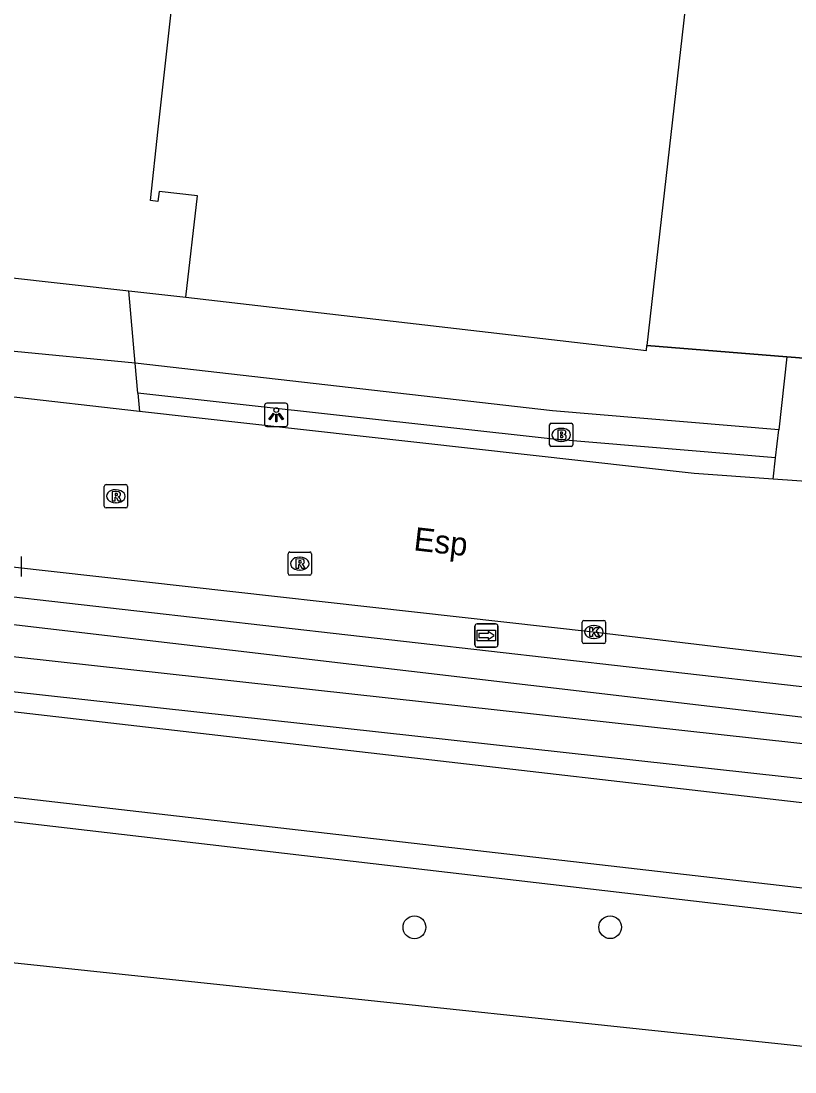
# Model space of a CAD drawing. Extents: x 161389 to 162585, y 388479 to 389761.
# Drawn here: x 162379.87 to 162413.12, y 388644.66 to 388689.82 of the extents above; entities that cross this region are included whole.
import ezdxf

# ---------------------------------------------------------------- set-up
doc = ezdxf.new("R2010")
doc.units = 0
for name, color, linetype in [('IMGEO_Berm_groen', 7, 'Continuous'), ('IMGEO_Boom', 7, 'Continuous'), ('IMGEO_Brandkraan', 7, 'Continuous'), ('IMGEO_Fietspad_gesloten', 7, 'Continuous'), ('IMGEO_Gemengd_bos', 7, 'Continuous'), ('IMGEO_Haag', 7, 'Continuous'), ('IMGEO_Hek', 7, 'Continuous'), ('IMGEO_Kolk', 7, 'Continuous'), ('IMGEO_Lichtpunt', 7, 'Continuous'), ('IMGEO_Openbare_ruimte_label', 7, 'Continuous'), ('IMGEO_Pand', 7, 'Continuous'), ('IMGEO_Rijbaan_lokaal_gesloten', 7, 'Continuous'), ('IMGEO_Rioolput', 7, 'Continuous'), ('IMGEO_Voetpad_open', 7, 'Continuous'), ('IMGEO_Waterloop', 7, 'Continuous'), ('IMGEO_Wegwijzer', 7, 'Continuous')]:
    doc.layers.add(name, color=color, linetype=linetype)

msp = doc.modelspace()

# ---------------------------------------------------------------- linework, layer by layer
at = {"layer": 'IMGEO_Berm_groen'}
for points in [[(162437.256, 388654.736), (162437.524, 388656.717), (162437.321, 388657.419), (162437.013, 388657.873), (162436.595, 388658.23), (162436.225, 388658.419), (162433.197, 388658.957), (162357.64, 388667.549)], [(162352.368, 388663.746), (162357.235, 388663.453), (162426.956, 388655.776), (162432.217, 388654.406), (162435.304, 388653.875)], [(162454.958, 388646.611), (162343.501, 388659.601)]]:
    msp.add_lwpolyline(points, dxfattribs=at)
at = {"layer": 'IMGEO_Boom'}
for centre in [(162396.77, 388650.877), (162405.18, 388650.883)]:
    msp.add_circle(centre, 0.489, dxfattribs=at)
at = {"layer": 'IMGEO_Brandkraan'}
for p, q in [((162402.578, 388671.612), (162402.578, 388672.464)), ((162402.653, 388672.538), (162403.505, 388672.538)), ((162403.066, 388672.318), (162403.091, 388672.318)), ((162403.579, 388672.464), (162403.579, 388671.612)), ((162403.505, 388671.538), (162402.653, 388671.538)), ((162403.089, 388671.758), (162403.064, 388671.758))]:
    msp.add_line(p, q, dxfattribs=at)
for points in [[(162402.578, 388671.612), (162402.578, 388672.464)], [(162402.653, 388672.538), (162403.505, 388672.538)], [(162403.579, 388672.464), (162403.579, 388671.612)], [(162402.926, 388672.238), (162402.926, 388671.838), (162403.139, 388671.838)], [(162403.157, 388672.238), (162402.926, 388672.238)], [(162403.105, 388672.157), (162403.051, 388672.157), (162403.051, 388672.081)], [(162403.051, 388672.081), (162403.104, 388672.081)], [(162403.113, 388672.005), (162403.051, 388672.005), (162403.051, 388671.924)], [(162403.051, 388671.924), (162403.113, 388671.924)], [(162403.505, 388671.538), (162402.653, 388671.538)]]:
    msp.add_lwpolyline(points, dxfattribs=at)
for centre, radius, start, end in [((162402.655, 388672.462), 0.0765, 91.552, 178.448), ((162402.655, 388672.462), 0.0765, 91.552, 178.448), ((162403.503, 388672.462), 0.0765, 1.552, 88.448), ((162403.503, 388672.462), 0.0765, 1.552, 88.448), ((162403.106, 388672.119), 0.0379, 267.8285, 90.9355), ((162403.114, 388671.964), 0.0404, 269.8759, 90.5077), ((162403.145, 388672.089), 0.251, 268.6676, 293.5347), ((162403.161, 388672.093), 0.145, 59.4692, 91.5367), ((162403.186, 388672.14), 0.0922, 285.5137, 58.1501), ((162403.191, 388671.948), 0.105, 301.3115, 78.989), ((162402.655, 388671.614), 0.0765, 181.552, 268.448), ((162402.655, 388671.614), 0.0765, 181.552, 268.448), ((162403.503, 388671.614), 0.0765, 271.552, 358.448), ((162403.503, 388671.614), 0.0765, 271.552, 358.448)]:
    msp.add_arc(centre, radius, start, end, dxfattribs=at)
for centre, major_axis, ratio, start_param, end_param in [((162403.065, 388672.038), (-0.387, 0.002), 0.722429, 4.712389, 7.853982), ((162403.09, 388672.038), (-0.39, 0.002), 0.717154, 1.570796, 4.712389)]:
    msp.add_ellipse(centre, major_axis=major_axis, ratio=ratio, start_param=start_param, end_param=end_param, dxfattribs=at)
at = {"layer": 'IMGEO_Fietspad_gesloten'}
for points in [[(162342.861, 388664.571), (162343.854, 388664.303), (162356.884, 388662.764), (162437.393, 388653.479), (162447.573, 388652.333)], [(162444.332, 388649.048), (162443.05, 388649.15), (162347.086, 388660.188)]]:
    msp.add_lwpolyline(points, dxfattribs=at)
at = {"layer": 'IMGEO_Gemengd_bos'}
msp.add_lwpolyline([(162341.543, 388653.38), (162458.56, 388641.004)], dxfattribs=at)
at = {"layer": 'IMGEO_Haag'}
for points in [[(162384.504, 388678.222), (162386.947, 388677.951)], [(162406.76, 388675.873), (162412.776, 388675.396)]]:
    msp.add_lwpolyline(points, dxfattribs=at)
at = {"layer": 'IMGEO_Hek'}
for points in [[(162412.776, 388675.396), (162406.76, 388675.873)], [(162420.122, 388674.813), (162412.776, 388675.396)]]:
    msp.add_lwpolyline(points, dxfattribs=at)
at = {"layer": 'IMGEO_Kolk'}
for p, q in [((162379.871, 388666.809), (162379.871, 388665.957)), ((162403.981, 388663.141), (162403.981, 388663.993)), ((162404.056, 388664.067), (162404.908, 388664.067)), ((162404.469, 388663.847), (162404.494, 388663.847)), ((162404.982, 388663.993), (162404.982, 388663.141)), ((162404.492, 388663.287), (162404.467, 388663.287)), ((162404.908, 388663.067), (162404.056, 388663.067))]:
    msp.add_line(p, q, dxfattribs=at)
for points in [[(162379.871, 388666.809), (162379.871, 388665.957)], [(162403.981, 388663.141), (162403.981, 388663.993)], [(162404.056, 388664.067), (162404.908, 388664.067)], [(162404.302, 388663.767), (162404.425, 388663.767), (162404.425, 388663.616), (162404.555, 388663.767), (162404.719, 388663.767), (162404.573, 388663.616), (162404.726, 388663.367), (162404.574, 388663.367), (162404.489, 388663.531), (162404.425, 388663.464), (162404.425, 388663.367), (162404.302, 388663.367), (162404.302, 388663.767)], [(162404.982, 388663.993), (162404.982, 388663.141)], [(162404.908, 388663.067), (162404.056, 388663.067)]]:
    msp.add_lwpolyline(points, dxfattribs=at)
for centre, start, end in [((162404.058, 388663.991), 91.552, 178.448), ((162404.058, 388663.991), 91.552, 178.448), ((162404.906, 388663.991), 1.552, 88.448), ((162404.906, 388663.991), 1.552, 88.448), ((162404.058, 388663.143), 181.552, 268.448), ((162404.058, 388663.143), 181.552, 268.448), ((162404.906, 388663.143), 271.552, 358.448), ((162404.906, 388663.143), 271.552, 358.448)]:
    msp.add_arc(centre, 0.0765, start, end, dxfattribs=at)
for centre, major_axis, ratio, start_param, end_param in [((162404.468, 388663.567), (-0.387, 0.002), 0.722429, 4.712389, 7.853982), ((162404.493, 388663.567), (-0.39, 0.002), 0.717154, 1.570796, 4.712389)]:
    msp.add_ellipse(centre, major_axis=major_axis, ratio=ratio, start_param=start_param, end_param=end_param, dxfattribs=at)
at = {"layer": 'IMGEO_Lichtpunt'}
for p, q in [((162390.337, 388673.304), (162390.337, 388672.497)), ((162390.337, 388673.304), (162390.337, 388672.497)), ((162391.239, 388673.399), (162390.431, 388673.399)), ((162391.239, 388673.399), (162390.431, 388673.399)), ((162391.333, 388672.497), (162391.333, 388673.304)), ((162391.333, 388672.497), (162391.333, 388673.304)), ((162390.431, 388672.403), (162391.239, 388672.403)), ((162390.431, 388672.403), (162391.239, 388672.403))]:
    msp.add_line(p, q, dxfattribs=at)
for points in [[(162390.711, 388672.968), (162390.75, 388672.94), (162390.562, 388672.678), (162390.524, 388672.705), (162390.711, 388672.968)], [(162390.813, 388672.92), (162390.86, 388672.92), (162390.86, 388672.598), (162390.813, 388672.598), (162390.813, 388672.92)], [(162390.923, 388672.94), (162390.961, 388672.967), (162391.148, 388672.705), (162391.109, 388672.677), (162390.923, 388672.94)]]:
    msp.add_lwpolyline(points, dxfattribs=at)
msp.add_circle((162390.836, 388673.102), 0.0994, dxfattribs=at)
for centre, start, end in [((162390.431, 388673.304), 90, 180), ((162390.431, 388673.304), 90, 180), ((162391.239, 388673.304), 0, 90), ((162391.239, 388673.304), 0, 90), ((162390.431, 388672.497), 180, 270), ((162390.431, 388672.497), 180, 270), ((162391.239, 388672.497), 270, 0), ((162391.239, 388672.497), 270, 360)]:
    msp.add_arc(centre, 0.0946, start, end, dxfattribs=at)
at = {"layer": 'IMGEO_Pand'}
for points in [[(162386.947, 388677.951), (162387.452, 388682.311), (162385.802, 388682.494), (162385.755, 388682.067), (162385.427, 388682.103), (162385.766, 388685.174), (162386.965, 388696.018), (162385.325, 388696.199), (162385.279, 388695.782), (162384.951, 388695.818), (162386.201, 388707.129), (162384.591, 388707.307), (162384.544, 388706.88), (162384.216, 388706.916), (162385.484, 388718.406), (162383.83, 388718.549), (162383.781, 388718.121), (162383.453, 388718.159), (162383.498, 388718.557), (162383.521, 388718.755), (162383.967, 388722.64), (162411.707, 388719.457), (162406.76, 388675.873)], [(162386.947, 388677.951), (162406.736, 388675.658), (162406.76, 388675.873)]]:
    msp.add_lwpolyline(points, dxfattribs=at)
at = {"layer": 'IMGEO_Rijbaan_lokaal_gesloten'}
for points in [[(162384.963, 388673.046), (162379.189, 388673.693)], [(162412.183, 388670.136), (162408.796, 388670.377), (162384.963, 388673.046)], [(162419.72, 388669.598), (162412.183, 388670.136)], [(162352.961, 388669.418), (162354.354, 388669.216), (162379.371, 388666.385), (162404.449, 388663.572), (162428.321, 388660.721), (162433.533, 388660.124), (162451.142, 388657.117), (162455.305, 388656.124), (162461.096, 388654.743), (162466.578, 388653.381), (162466.865, 388653.311)]]:
    msp.add_lwpolyline(points, dxfattribs=at)
at = {"layer": 'IMGEO_Rioolput'}
for p, q in [((162383.448, 388668.972), (162383.448, 388669.824)), ((162383.523, 388669.898), (162384.375, 388669.898)), ((162383.936, 388669.678), (162383.961, 388669.678)), ((162384.449, 388669.824), (162384.449, 388668.972)), ((162384.375, 388668.898), (162383.523, 388668.898)), ((162383.959, 388669.118), (162383.934, 388669.118)), ((162391.346, 388666.078), (162391.346, 388666.93)), ((162391.421, 388667.004), (162392.273, 388667.004)), ((162392.347, 388666.93), (162392.347, 388666.078)), ((162391.834, 388666.784), (162391.859, 388666.784)), ((162392.273, 388666.004), (162391.421, 388666.004)), ((162391.857, 388666.224), (162391.832, 388666.224))]:
    msp.add_line(p, q, dxfattribs=at)
for points in [[(162383.448, 388668.972), (162383.448, 388669.824)], [(162383.523, 388669.898), (162384.375, 388669.898)], [(162384.037, 388669.596), (162383.785, 388669.598), (162383.785, 388669.198)], [(162384.449, 388669.824), (162384.449, 388668.972)], [(162383.785, 388669.198), (162383.909, 388669.198), (162383.909, 388669.36), (162383.92, 388669.36)], [(162383.963, 388669.517), (162383.909, 388669.517), (162383.909, 388669.436)], [(162383.909, 388669.436), (162383.961, 388669.436)], [(162383.967, 388669.331), (162384.038, 388669.198), (162384.178, 388669.198), (162384.113, 388669.324)], [(162384.375, 388668.898), (162383.523, 388668.898)], [(162391.346, 388666.078), (162391.346, 388666.93)], [(162391.421, 388667.004), (162392.273, 388667.004)], [(162392.347, 388666.93), (162392.347, 388666.078)], [(162391.935, 388666.702), (162391.683, 388666.704), (162391.683, 388666.304)], [(162391.683, 388666.304), (162391.807, 388666.304), (162391.807, 388666.466), (162391.818, 388666.466)], [(162391.861, 388666.623), (162391.807, 388666.623), (162391.807, 388666.542)], [(162391.807, 388666.542), (162391.859, 388666.542)], [(162391.865, 388666.437), (162391.936, 388666.304), (162392.076, 388666.304), (162392.011, 388666.43)], [(162392.273, 388666.004), (162391.421, 388666.004)]]:
    msp.add_lwpolyline(points, dxfattribs=at)
for centre, radius, start, end in [((162383.525, 388669.822), 0.0765, 91.552, 178.448), ((162383.525, 388669.822), 0.0765, 91.552, 178.448), ((162384.036, 388669.486), 0.109, 350.3612, 89.416), ((162384.373, 388669.822), 0.0765, 1.552, 88.448), ((162384.373, 388669.822), 0.0765, 1.552, 88.448), ((162383.919, 388669.307), 0.0533, 26.0293, 88.6989), ((162383.945, 388669.625), 0.19, 274.7715, 282.9687), ((162383.969, 388669.421), 0.0964, 77.0061, 93.1865), ((162383.983, 388669.478), 0.0378, 276.6634, 79.6772), ((162384.034, 388669.486), 0.112, 277.5842, 350.9817), ((162384.018, 388669.271), 0.108, 29.5134, 73.7905), ((162383.525, 388668.974), 0.0765, 181.552, 268.448), ((162383.525, 388668.974), 0.0765, 181.552, 268.448), ((162384.373, 388668.974), 0.0765, 271.552, 358.448), ((162384.373, 388668.974), 0.0765, 271.552, 358.448), ((162391.423, 388666.928), 0.0765, 91.552, 178.448), ((162391.423, 388666.928), 0.0765, 91.552, 178.448), ((162392.271, 388666.928), 0.0765, 1.552, 88.448), ((162392.271, 388666.928), 0.0765, 1.552, 88.448), ((162391.817, 388666.413), 0.0533, 26.0293, 88.6989), ((162391.843, 388666.731), 0.19, 274.7715, 282.9687), ((162391.867, 388666.527), 0.0964, 77.0061, 93.1865), ((162391.881, 388666.584), 0.0378, 276.6634, 79.6772), ((162391.934, 388666.592), 0.109, 350.3612, 89.416), ((162391.932, 388666.592), 0.112, 277.5842, 350.9817), ((162391.916, 388666.377), 0.108, 29.5134, 73.7905), ((162391.423, 388666.08), 0.0765, 181.552, 268.448), ((162391.423, 388666.08), 0.0765, 181.552, 268.448), ((162392.271, 388666.08), 0.0765, 271.552, 358.448), ((162392.271, 388666.08), 0.0765, 271.552, 358.448)]:
    msp.add_arc(centre, radius, start, end, dxfattribs=at)
for centre, major_axis, ratio, start_param, end_param in [((162383.935, 388669.398), (-0.387, 0.002), 0.722429, 4.712389, 7.853982), ((162383.96, 388669.398), (-0.39, 0.002), 0.717154, 1.570796, 4.712389), ((162391.833, 388666.504), (-0.387, 0.002), 0.722429, 4.712389, 7.853982), ((162391.858, 388666.504), (-0.39, 0.002), 0.717154, 1.570796, 4.712389)]:
    msp.add_ellipse(centre, major_axis=major_axis, ratio=ratio, start_param=start_param, end_param=end_param, dxfattribs=at)
at = {"layer": 'IMGEO_Voetpad_open'}
for points in [[(162379.117, 388678.821), (162384.504, 388678.222)], [(162384.771, 388675.111), (162384.504, 388678.222)], [(162384.771, 388675.111), (162379.154, 388675.665)], [(162384.891, 388673.825), (162384.771, 388675.111)], [(162412.421, 388672.249), (162402.707, 388673.075), (162384.771, 388675.111)], [(162412.776, 388675.396), (162412.421, 388672.249)], [(162412.776, 388675.396), (162420.122, 388674.813)], [(162384.891, 388673.825), (162384.963, 388673.046)], [(162412.286, 388671.047), (162402.725, 388671.854), (162384.891, 388673.825)], [(162412.286, 388671.047), (162412.421, 388672.249)], [(162412.183, 388670.136), (162412.286, 388671.047)]]:
    msp.add_lwpolyline(points, dxfattribs=at)
at = {"layer": 'IMGEO_Waterloop'}
for points in [[(162352.987, 388666.821), (162353.241, 388666.814), (162357.696, 388666.45), (162433.015, 388657.61), (162435.457, 388657.224)], [(162435.326, 388655.82), (162435.12, 388655.826), (162427.37, 388657.224), (162357.525, 388664.915), (162352.705, 388665.205)]]:
    msp.add_lwpolyline(points, dxfattribs=at)
at = {"layer": 'IMGEO_Wegwijzer'}
for p, q in [((162399.367, 388663.017), (162399.367, 388663.817)), ((162399.367, 388663.817), (162399.367, 388663.017)), ((162399.467, 388663.917), (162400.257, 388663.917)), ((162400.257, 388663.917), (162399.467, 388663.917)), ((162400.357, 388663.817), (162400.357, 388663.017)), ((162400.357, 388663.017), (162400.357, 388663.817)), ((162400.257, 388662.917), (162399.467, 388662.917)), ((162399.467, 388662.917), (162400.257, 388662.917))]:
    msp.add_line(p, q, dxfattribs=at)
for points in [[(162399.468, 388663.649), (162400.256, 388663.649), (162400.256, 388663.185), (162399.468, 388663.185), (162399.468, 388663.649)], [(162399.533, 388663.501), (162399.533, 388663.417), (162399.533, 388663.333), (162399.944, 388663.333), (162399.944, 388663.25), (162400.191, 388663.417), (162399.944, 388663.584), (162399.944, 388663.501), (162399.533, 388663.501)]]:
    msp.add_lwpolyline(points, dxfattribs=at)
for centre, start, end in [((162399.467, 388663.817), 90, 180), ((162399.467, 388663.817), 90, 180), ((162400.257, 388663.817), 0, 90), ((162400.257, 388663.817), 360, 90), ((162399.467, 388663.017), 180, 270), ((162399.467, 388663.017), 180, 270), ((162400.257, 388663.017), 270, 0), ((162400.257, 388663.017), 270, 0)]:
    msp.add_arc(centre, 0.1, start, end, dxfattribs=at)

# ---------------------------------------------------------------- texts
at = {"layer": 'IMGEO_Openbare_ruimte_label'}
msp.add_text('Esp', height=1, rotation=353.5143, dxfattribs=at).set_placement((162396.71, 388667.082))

doc.saveas('drawing.dxf')
